// Mitsubishi GX Works2 project: MODBUS_MASTER_v3   PLC: FX3G

// task Task_01 (event TRUE, interval 0, priority 31): POU_01
// user libraries (not included): moddus_ser

PROGRAM POU_01
VAR
  MODBUS_FB_MASTER_v2_1 : MODBUS_FB_MASTER_v2;
END_VAR
(* structured ladder/FBD written out as ST: instructions are called as NAME(EN, inputs, outputs); _pN, _eN, _tN stand for wires *)
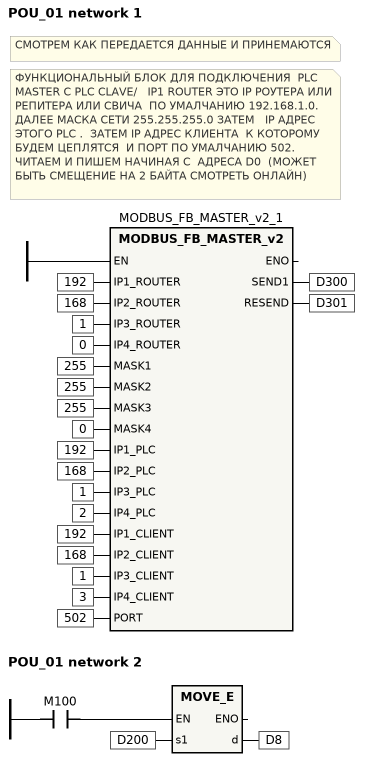
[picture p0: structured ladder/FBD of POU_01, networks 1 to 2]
(* network 1 *)
(* СМОТРЕМ КАК ПЕРЕДАЕТСЯ ДАННЫЕ И ПРИНЕМАЮТСЯ *)
(* ФУНКЦИОНАЛЬНЫЙ БЛОК ДЛЯ ПОДКЛЮЧЕНИЯ  PLC MASTER C PLC CLAVE/   IP1 ROUTER ЭТО IP РОУТЕРА ИЛИ РЕПИТЕРА ИЛИ СВИЧА  ПО УМАЛЧАНИЮ 192.168.1.0.   ДАЛЕЕ МАСКА СЕТИ 255.255.255.0 ЗАТЕМ   IP АДРЕС  ЭТОГО PLC .  ЗАТЕМ IP АДРЕС КЛИЕНТА  К КОТОРОМУ БУДЕМ ЦЕПЛЯТСЯ  И ПОРТ ПО УМАЛЧАНИЮ 502.     ЧИТАЕМ И ПИШЕМ НАЧИНАЯ С  АДРЕСА D0  (МОЖЕТ БЫТЬ СМЕЩЕНИЕ НА 2 БАЙТА СМОТРЕТЬ ОНЛАЙН) *)
MODBUS_FB_MASTER_v2_1(EN := TRUE, IP1_ROUTER := 192, IP2_ROUTER := 168, IP3_ROUTER := 1, IP4_ROUTER := 0, MASK1 := 255, MASK2 := 255, MASK3 := 255, MASK4 := 0, IP1_PLC := 192, IP2_PLC := 168, IP3_PLC := 1, IP4_PLC := 2, IP1_CLIENT := 192, IP2_CLIENT := 168, IP3_CLIENT := 1, IP4_CLIENT := 3, PORT := 502, SEND1 => D300, RESEND => D301);
(* network 2 *)
MOVE_E(M100, D200, D8);
END_PROGRAM

FUNCTION_BLOCK MODBUS_FB_MASTER_v2
VAR_INPUT
  IP1_ROUTER : INT;
  IP2_ROUTER : INT;
  IP3_ROUTER : INT;
  IP4_ROUTER : INT;
  MASK1 : INT;
  MASK2 : INT;
  MASK3 : INT;
  MASK4 : INT;
  IP1_PLC : INT;
  IP2_PLC : INT;
  IP3_PLC : INT;
  IP4_PLC : INT;
END_VAR
VAR_OUTPUT
  SEND1 : INT;
  RESEND : INT;
END_VAR
VAR_INPUT
  IP1_CLIENT : INT;
  IP2_CLIENT : INT;
  IP3_CLIENT : INT;
  IP4_CLIENT : INT;
  PORT : INT;
END_VAR
(* structured ladder/FBD written out as ST: instructions are called as NAME(EN, inputs, outputs); _pN, _eN, _tN stand for wires *)
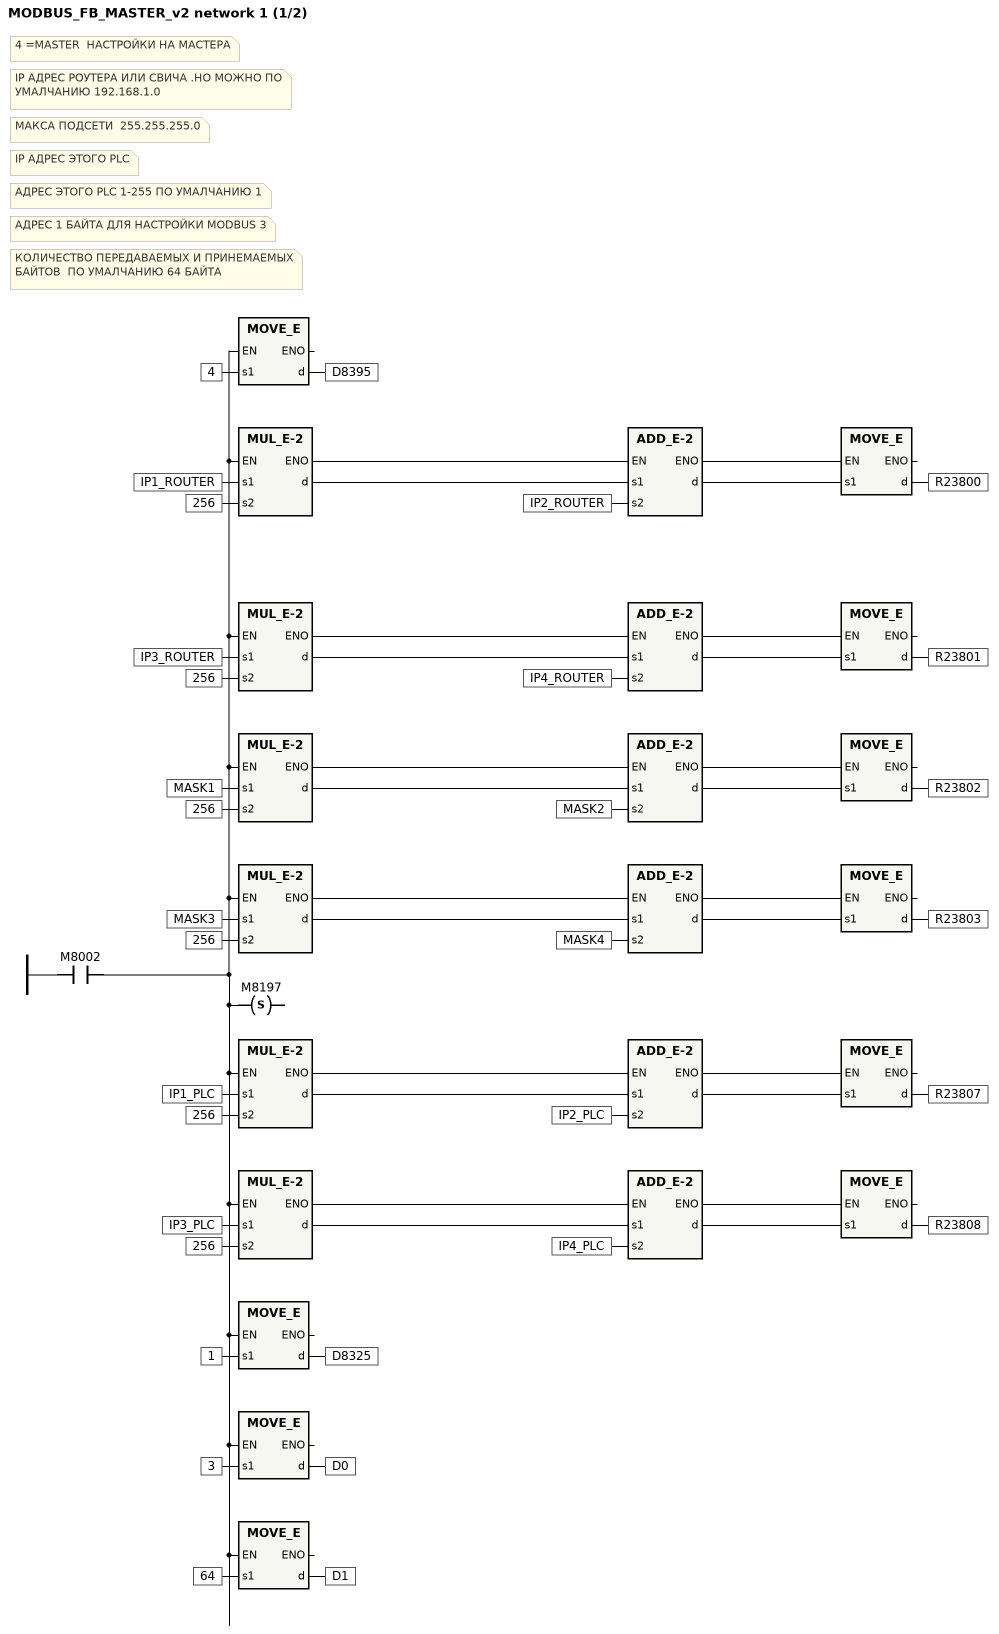
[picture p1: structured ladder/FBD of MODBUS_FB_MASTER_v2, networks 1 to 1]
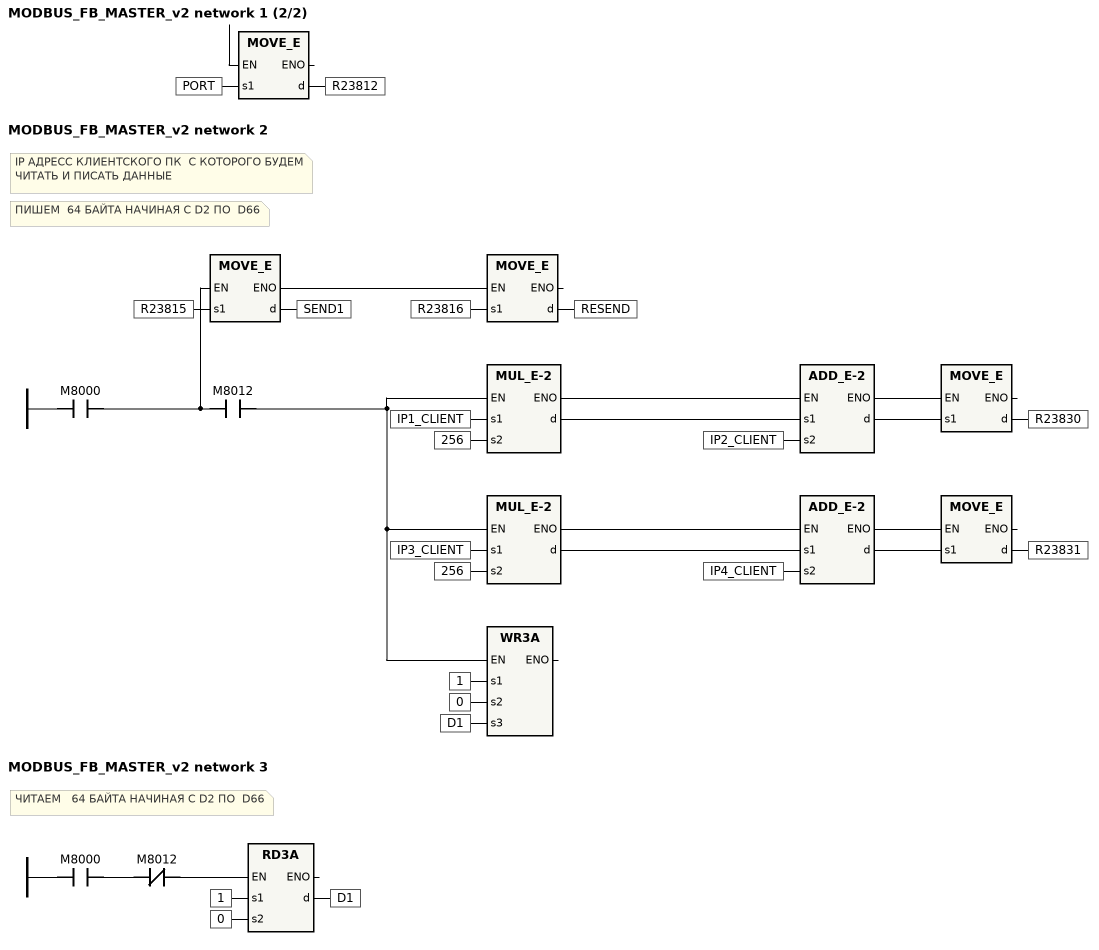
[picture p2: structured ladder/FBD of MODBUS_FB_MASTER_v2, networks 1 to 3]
(* network 1 *)
(* 4 =MASTER  НАСТРОЙКИ НА МАСТЕРА *)
(* IP АДРЕС РОУТЕРА ИЛИ СВИЧА .НО МОЖНО ПО УМАЛЧАНИЮ 192.168.1.0 *)
(* МАКСА ПОДСЕТИ  255.255.255.0 *)
(* IP АДРЕС ЭТОГО PLC *)
(* АДРЕС ЭТОГО PLC 1-255 ПО УМАЛЧАНИЮ 1 *)
(* АДРЕС 1 БАЙТА ДЛЯ НАСТРОЙКИ MODBUS 3 *)
(* КОЛИЧЕСТВО ПЕРЕДАВАЕМЫХ И ПРИНЕМАЕМЫХ БАЙТОВ  ПО УМАЛЧАНИЮ 64 БАЙТА *)
MOVE_E(M8002, 4, D8395);
SET(M8002, M8197);
_e2 := MUL_E(M8002, IP1_ROUTER, 256, _t1);
_e4 := ADD_E(_e2, _t1, IP2_ROUTER, _t3);
MOVE_E(_e4, _t3, R23800);
_e6 := MUL_E(M8002, IP3_ROUTER, 256, _t5);
_e8 := ADD_E(_e6, _t5, IP4_ROUTER, _t7);
MOVE_E(_e8, _t7, R23801);
_e10 := MUL_E(M8002, MASK1, 256, _t9);
_e12 := ADD_E(_e10, _t9, MASK2, _t11);
MOVE_E(_e12, _t11, R23802);
_e14 := MUL_E(M8002, MASK3, 256, _t13);
_e16 := ADD_E(_e14, _t13, MASK4, _t15);
MOVE_E(_e16, _t15, R23803);
_e18 := MUL_E(M8002, IP1_PLC, 256, _t17);
_e20 := ADD_E(_e18, _t17, IP2_PLC, _t19);
MOVE_E(_e20, _t19, R23807);
_e22 := MUL_E(M8002, IP3_PLC, 256, _t21);
_e24 := ADD_E(_e22, _t21, IP4_PLC, _t23);
MOVE_E(_e24, _t23, R23808);
MOVE_E(M8002, 1, D8325);
MOVE_E(M8002, 3, D0);
MOVE_E(M8002, 64, D1);
MOVE_E(M8002, PORT, R23812);
(* network 2 *)
(* IP АДРЕСС КЛИЕНТСКОГО ПК  С КОТОРОГО БУДЕМ ЧИТАТЬ И ПИСАТЬ ДАННЫЕ *)
(* ПИШЕМ  64 БАЙТА НАЧИНАЯ С D2 ПО  D66 *)
_e1 := MOVE_E(M8000, R23815, SEND1);
MOVE_E(_e1, R23816, RESEND);
_p2 := M8000 AND M8012;
_e4 := MUL_E(_p2, IP1_CLIENT, 256, _t3);
_e6 := ADD_E(_e4, _t3, IP2_CLIENT, _t5);
MOVE_E(_e6, _t5, R23830);
_e8 := MUL_E(_p2, IP3_CLIENT, 256, _t7);
_e10 := ADD_E(_e8, _t7, IP4_CLIENT, _t9);
MOVE_E(_e10, _t9, R23831);
WR3A(_p2, 1, 0, D1);
(* network 3 *)
(* ЧИТАЕМ   64 БАЙТА НАЧИНАЯ С D2 ПО  D66 *)
RD3A(M8000 AND NOT M8012, 1, 0, D1);
END_FUNCTION_BLOCK
